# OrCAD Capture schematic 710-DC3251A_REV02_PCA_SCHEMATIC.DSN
size B; title: 3.3V TO 1.2V AT 2A 2MHz SYNCHRONOUS
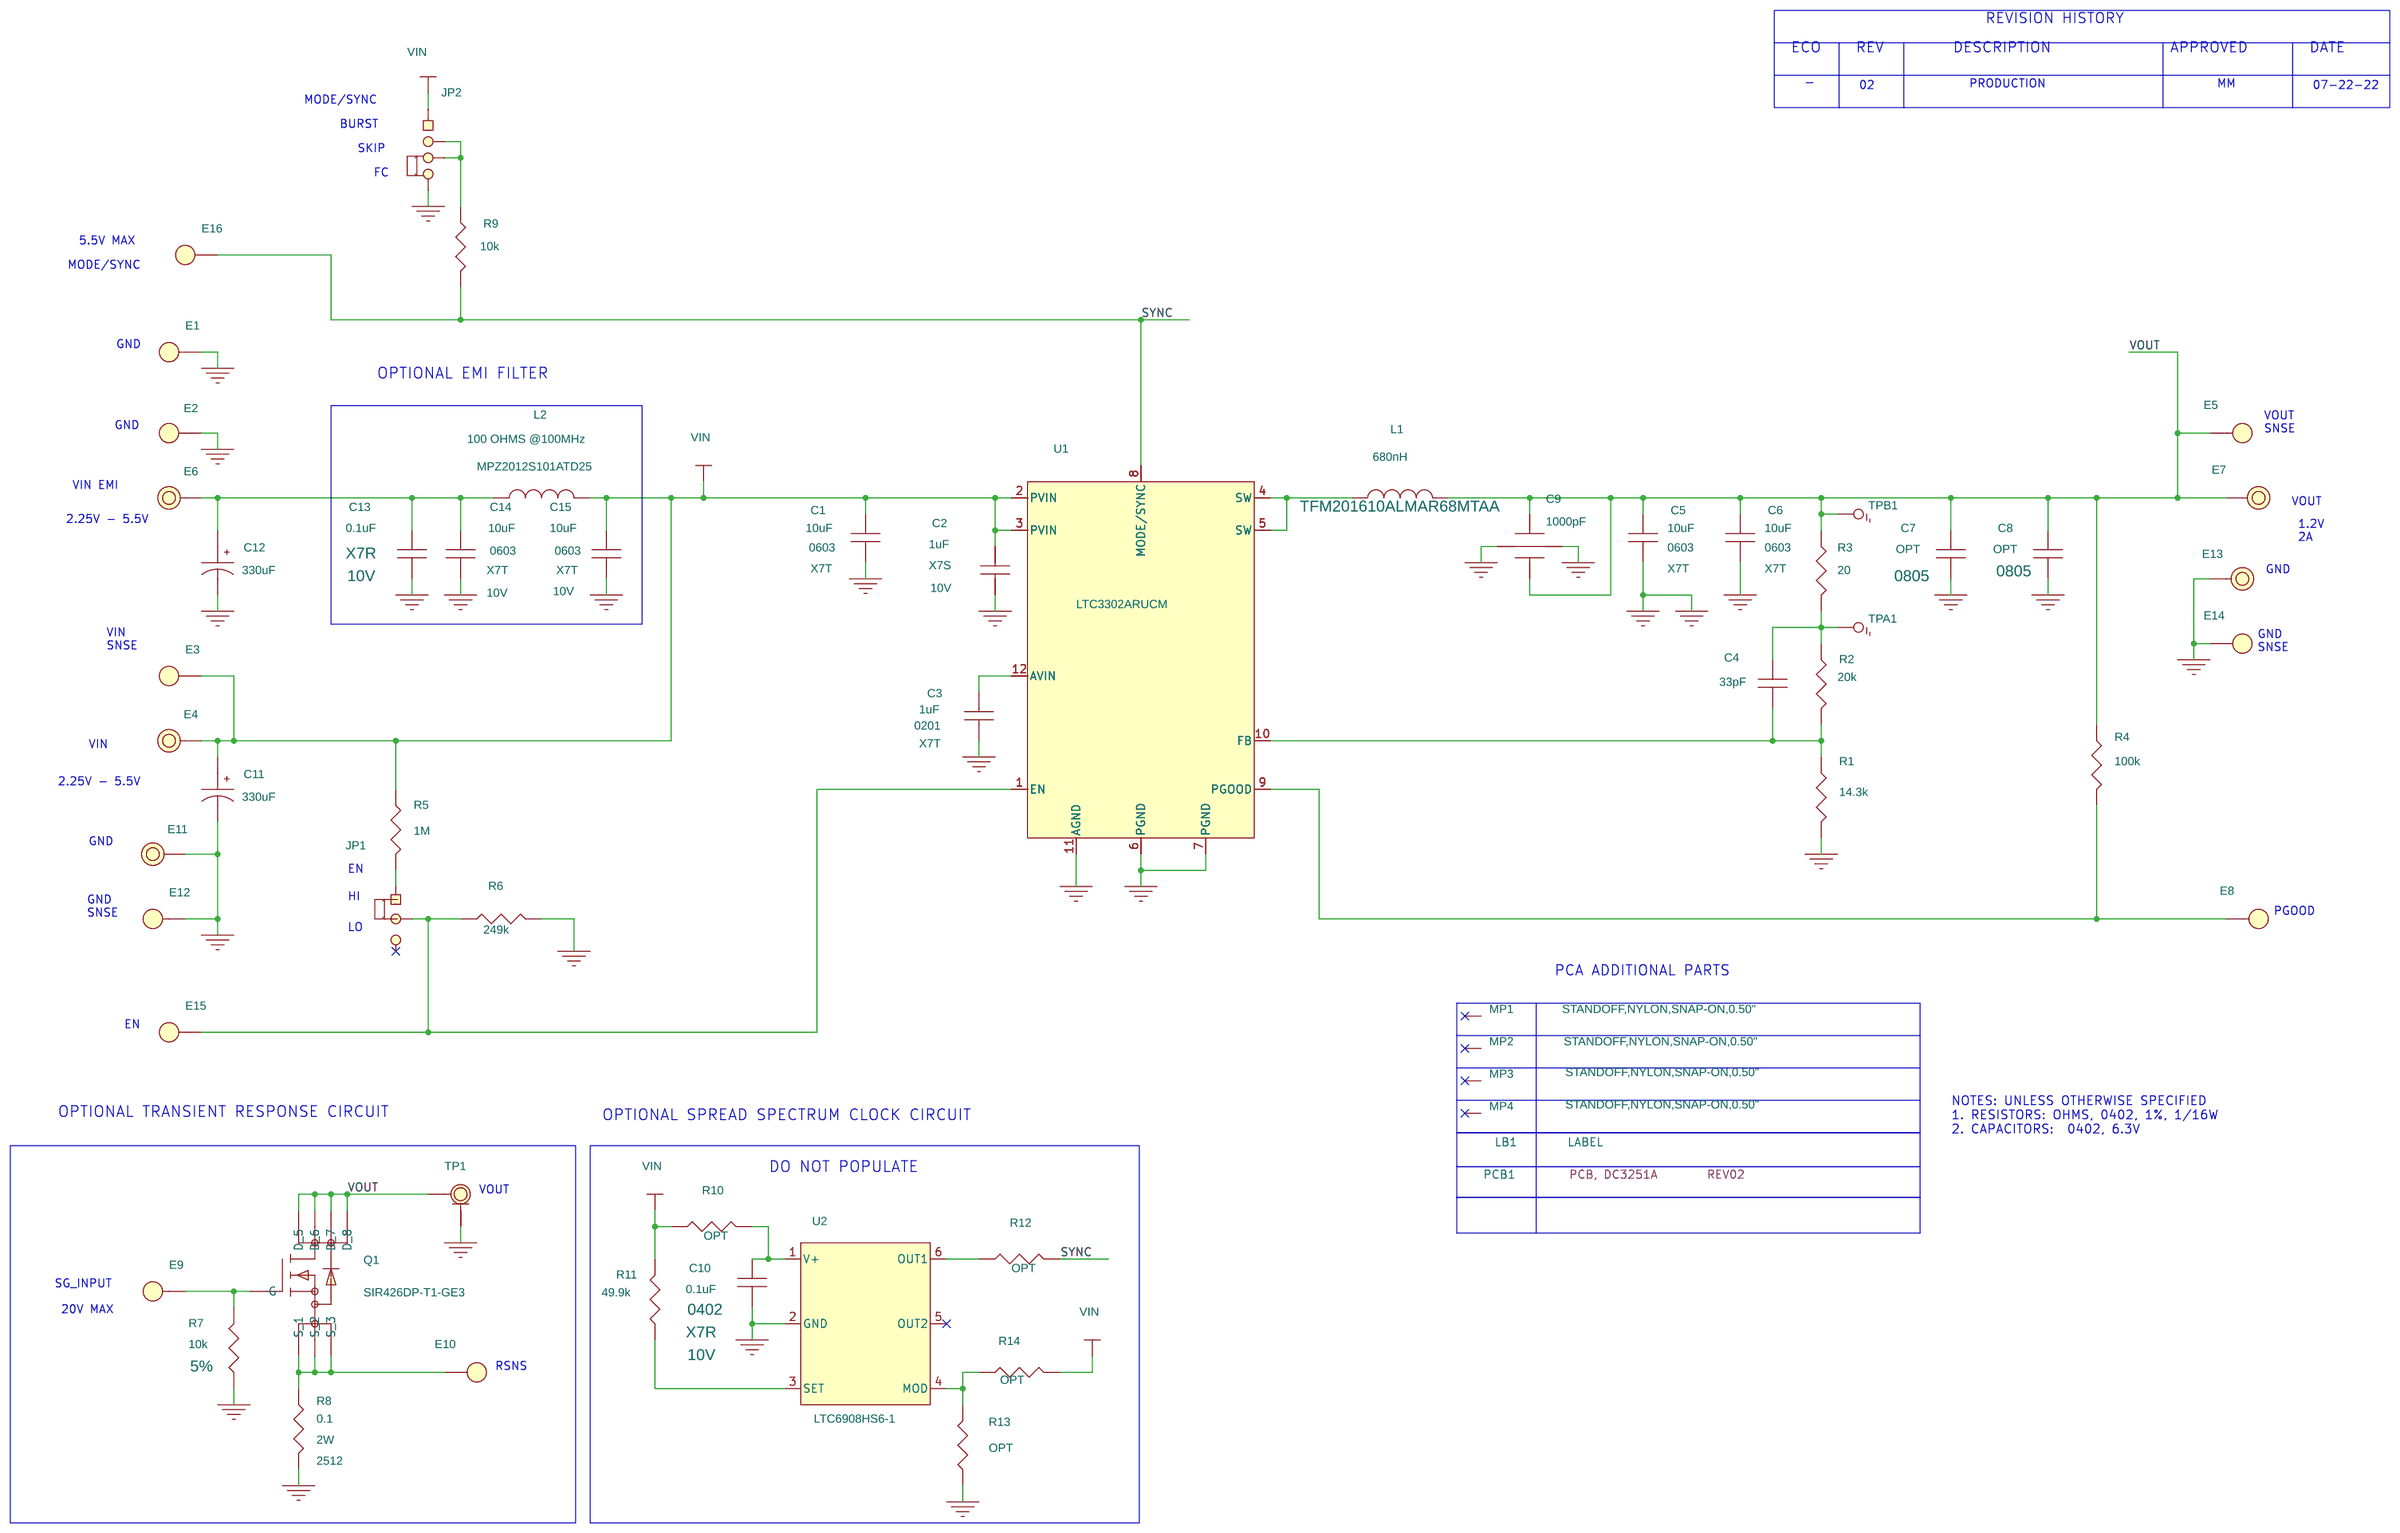
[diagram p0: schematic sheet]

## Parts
C1  10uF  [CC0603N]
C2  1uF  [CC0402N]
C3  1uF  [CC0201M]
C4  33pF  [CC0402N]
C5  10uF  [CC0603N]
C6  10uF  [CC0603N]
C7  OPT  [CC0805N]
C8  OPT  [CC0805N]
C9  1000pF  [JOHANSON-X2Y-X07]
C10  0.1uF  [CC0402N]
C11  330uF  [CAPMP7343N]
C12  330uF  [CAPMP7343N]
C13  0.1uF  [CC0402N]
C14  10uF  [CC0603N]
C15  10uF  [CC0603N]
E1  TEST POINT  [MILLMAX2308]
E2  TEST POINT  [MILLMAX2308]
E3  TEST POINT  [MILLMAX2308]
E4  TEST POINT  [MILLMAX2501]
E5  TEST POINT  [MILLMAX2308]
E6  TEST POINT  [MILLMAX2501]
E7  TEST POINT  [MILLMAX2501]
E8  TEST POINT  [MILLMAX2308]
E9  TEST POINT  [MILLMAX2308]
E10  TEST POINT  [MILLMAX2308]
E11  TEST POINT  [MILLMAX2501]
E12  TEST POINT  [MILLMAX2308]
E13  TEST POINT  [MILLMAX2501]
E14  TEST POINT  [MILLMAX2308]
E15  TEST POINT  [MILLMAX2308]
E16  TEST POINT  [MILLMAX2308]
JP1  HDR  [HD1X3-079]
JP2  HDR  [JP4X1/079]
L1  680nH  [TDK-TFM201610ALMA]
L2  100 OHMS @100MHz  [IND0805N]
LB1  LABEL  [895-0154_REV01]
MP1  STANDOFF  [MTG-8831]
MP2  STANDOFF  [MTG-8831]
MP3  STANDOFF  [MTG-8831]
MP4  STANDOFF  [MTG-8831]
PCB1  PCB, DC3251A
Q1  SIR426DP-T1-GE3  [VISHAY_PPAK_SO-8]
R1  14.3k  [CR0402N]
R2  20k  [CR0402N]
R3  20  [CR0402N]
R4  100k  [CR0402N]
R5  1M  [CR0402N]
R6  249k  [CR0402N]
R7  10k  [CR0402N]
R8  0.1  [CR2512N]
R9  10k  [CR0402N]
R10  OPT  [CR0402N]
R11  49.9k  [CR0402N]
R12  OPT  [CR0402N]
R13  OPT  [CR0402N]
R14  OPT  [CR0402N]
TP1  U.FL  [HIROSE-FL-R-SMT-1]
TPA1  COPPER FEATURE PAD  [PADSTYLE1]
TPB1  COPPER FEATURE PAD  [PADSTYLE1]
U1  LTC3302ARUCM  [LTC-UCM-12-7072]
U2  LTC6908HS6-1  [LTC-S6-6-1636]
XJP1  SHUNT
XJP2  SHUNT

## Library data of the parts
C1 C5 C6 C14 C15 = CAP: CAP.,10uF,X7T,10V,20%,0603,AEC-Q200; CLASS: DISCRETE; Dielectric Type: X7T; FPLIST: CC0603N,CC0603L,CC0603M; Inventory Qty: 0; Manufacturer: MURATA; Manufacturer PN: GRT188D71A106ME13D; PART_NUMBER: 150-1887; Package Size: 0603; Rated Voltage: 10V; Tolerance: 20%
C2 = CAP: CAP.,1uF,X7S,10V,10%,0402,AEC-Q200,NO SUBS. ALLOWED; CLASS: DISCRETE; Dielectric Type: X7S; FPLIST: CC0402N,CC0402L,CC0402M; Inventory Qty: 10000; Manufacturer: MURATA; Manufacturer PN: GCM155C71A105KE38D; PART_NUMBER: 150-0594; Package Size: 0402; Rated Voltage: 10V; Temperature Coefficient: X7S; Tolerance: 10%
C3 = CAP: CAP.,1uF,X7T,6.3V,20%,0201,AEC-Q200; CLASS: DISCRETE; Dielectric Type: X7T; FPLIST: CC0201N,CC0201L,CC0201M; Inventory Qty: 0; Manufacturer: MURATA; Manufacturer PN: GRT033D70J105ME13D; PART_NUMBER: 150-1886; Package Size: 0201; Rated Voltage: 6.3V; Tolerance: 20%
C4 = CAP: CAP.,33pF,C0G,50V,5%,0402; CLASS: DISCRETE; Dielectric Type: C0G; FPLIST: CC0402N,CC0402L,CC0402M; Inventory Qty: 24223; Manufacturer: AVX; Manufacturer PN: 04025A330JAT2A; PART_NUMBER: 150-0066; Package Size: 0402; Rated Voltage: 50V; Tolerance: 5%
C7 C8 = CAP: CAP., OPTION, 0805; CLASS: DISCRETE; FPLIST: CC0805N,CC0805L,CC0805M; PART_NUMBER: 150-3036; Package Size: 0805; Package Type: SMD
C9 = JOHANSON-X2Y: CAP.,1000pF,X7R,50V,20%,0402,3-TERM,X2Y EMI FILTER; CLASS: DISCRETE; Dielectric Type: X7R; Inventory Qty: 16829; Manufacturer: JOHANSON DIELECTRICS; Manufacturer PN: 500X07W102MV4T; PART_NUMBER: 150-1785; Package Size: 0402,3-TERM; Rated Voltage: 50V; Tolerance: 20%
C10 C13 = CAP: CAP.,0.1uF,X7R,10V,10%,0402,AEC-Q200; CLASS: DISCRETE; Dielectric Type: X7R; FPLIST: CC0402N,CC0402L,CC0402M; Inventory Qty: 59100; Manufacturer: MURATA; Manufacturer PN: GCM155R71A104KA55D; PART_NUMBER: 150-1790; Package Size: 0402; Rated Voltage: 10V; Temperature Coefficient: X7R; Tolerance: 10%
C11 C12 = CAP_P_ALT: CAP.,330uF,TANT,POSCAP,6.3V,20%,7343,25mOHMS,TPE; CLASS: DISCRETE; Dielectric Type: TANT,POSCAP; Inventory Qty: 3750; Manufacturer: PANASONIC; Manufacturer PN: 6TPE330ML; PART_NUMBER: 150-0529; Package Size: 7343; Rated Voltage: 6.3V; Tolerance: 20%; UserField01: 2400mAms, 25mOHMS
E1-E3 E5 E8-E10 E12 E14-E16 = TEST_POINT_.156_MILL-MAX_2308: TEST POINT,TURRET,0.064" MTG. HOLE,PCB 0.062" THK; CLASS: IO; Inventory Qty: 1142083; Manufacturer PN: 2308-2-00-80-00-00-07-0; PART_NUMBER: 260-0004
E4 E6 E7 E11 E13 = TESTPOINT_.219_MILL-MAX_2501: TEST POINT,TURRET,0.094" MTG. HOLE,PCB 0.062" THK; CLASS: IO; FPLIST: MILLMAX2501,MILLMAX2501-2; Inventory Qty: 823526; Manufacturer: MILL-MAX; Manufacturer PN: 2501-2-00-80-00-00-07-0; PART_NUMBER: 260-0003
JP1 = 3_PIN_HEADER_.079_SINGLE_ROW_D: CONN.,HDR,MALE,1x3,2mm,VERT,ST,THT; CLASS: IO; Inventory Qty: 22026; Manufacturer: Wurth Elektronik; Manufacturer PN: 62000311121; PART_NUMBER: 250-0484
JP2 = HD1X4-079_ALT: CONN.,HDR,MALE,1x4,2mm,VERT,ST,THT; CLASS: IO; Inventory Qty: 12591; Manufacturer: WURTH ELEKTRONIK; Manufacturer PN: 62000411121; PART_NUMBER: 250-0563
L1 = IND_ALT: IND.,680nH,PWR,20%,4.3A,53mOHMS,0806,AEC-Q200; CLASS: DISCRETE; Inventory Qty: 0; Manufacturer: TDK; Manufacturer PN: TFM201610ALMAR68MTAA; PART_NUMBER: 200-0430; Package Size: 0806; Tolerance: 20%
L2 = IND_ALT: IND.,100 OHMS @100MHz,FERRITE BEAD,25%,4A,20mOHMS,0805,AEC-Q200; CLASS: DISCRETE; FPLIST: IND0805N,IND0805L,IND0805M; Inventory Qty: 0; Manufacturer: TDK; Manufacturer PN: MPZ2012S101ATD25; PART_NUMBER: 200-0403; Package Size: 0805; Tolerance: 25%
LB1 = BLANK_LABEL: LABEL SPEC, DEMO BOARD SERIAL NUMBER; Inventory Qty: 0; Manufacturer: BRADY; Manufacturer PN: THT-96-717-10; PART_NUMBER: 895-0154
MP1-MP4 = MP-PINNED_ALT1: STANDOFF,NYLON,SNAP-ON,0.50"; CLASS: DISCRETE; Inventory Qty: 214842; Manufacturer: KEYSTONE; Manufacturer PN: 8833; PART_NUMBER: 763-0007
PCB1 = BLANK_PCB_PART: BOM Notes: REV02; CLASS: DISCRETE; Inventory Qty: 0; Manufacturer: ADI APPROVED SUPPLIER; Manufacturer PN: 600-DC3251A; PART_NUMBER: 600-DC3251A
Q1 = 8P_N-CH_TYPE1A: XSTR.,MOSFET,N-CH,40V,15.9A,PPAK SO-8; CLASS: DISCRETE; Inventory Qty: 20200; Manufacturer: VISHAY; PART_NUMBER: 240-0378; Package Size: PowerPAK® SO-8; Package Type: PPAK SO-8; Polarity: MOSFET N-Channel; Rated Power: 41.7W; Rated Voltage: 40V
R1 = RES: RES.,14.3k OHMS,1%,1/16W,0402; CLASS: DISCRETE; FPLIST: CR0402N,CR0402L,CR0402M; Inventory Qty: 9613; Manufacturer: VISHAY; Manufacturer PN: CRCW040214K3FKED; PART_NUMBER: 100-0029; Package Size: 0402; Rated Power: 1/16W; Temperature Coefficient: 100ppm; Tolerance: 1%
R2 = RES: RES.,20k OHMS,1%,1/16W,0402,AEC-Q200; CLASS: DISCRETE; FPLIST: CR0402N,CR0402L,CR0402M; Inventory Qty: 11520; Manufacturer: NIC; Manufacturer PN: NRC04F2002TRF; PART_NUMBER: 100-2549; Package Size: 0402; Rated Power: 1/16W; Temperature Coefficient: 100ppm/C; Tolerance: 1%
R3 = RES: RES.,20 OHMS,1%,1/16W,0402,AEC-Q200; CLASS: DISCRETE; FPLIST: CR0402N,CR0402L,CR0402M; Inventory Qty: 29845; Manufacturer: NIC; Manufacturer PN: NRC04F20R0TRF; PART_NUMBER: 100-0250; Package Size: 0402; Rated Power: 1/16W; Temperature Coefficient: 100ppm; Tolerance: 1%
R4 = RES: RES.,100k OHMS,5%,1/16W,0402; CLASS: DISCRETE; FPLIST: CR0402N,CR0402L,CR0402M; Inventory Qty: 91623; Manufacturer: YAGEO; Manufacturer PN: RC0402JR-07100KL; PART_NUMBER: 100-0058; Package Size: 0402; Rated Power: 1/16W; Temperature Coefficient: 100ppm/C; Tolerance: 5%
R5 = RES: RES.,1M OHM,1%,1/16W,0402,AEC-Q200; CLASS: DISCRETE; FPLIST: CR0402N,CR0402L,CR0402M; Inventory Qty: 86432; Manufacturer: STACKPOLE ELECTRONICS, INC.; Manufacturer PN: RMCF0402FT1M00; PART_NUMBER: 100-2457; Package Size: 0402; Rated Power: 1/16W; Temperature Coefficient: 100ppm; Tolerance: 1%
R6 = RES: RES.,249k OHMS,1%,1/16W,0402,AEC-Q200; CLASS: DISCRETE; FPLIST: CR0402N,CR0402L,CR0402M; Inventory Qty: 26713; Manufacturer: NIC; Manufacturer PN: NRC04F2493TRF; PART_NUMBER: 100-2663; Package Size: 0402; Rated Power: 1/16W; Temperature Coefficient: 100ppm; Tolerance: 1%
R7 = RES: RES.,10k OHMS,5%,1/10W,0402,AEC-Q200; CLASS: DISCRETE; FPLIST: CR0402N,CR0402L,CR0402M; Inventory Qty: 33211; Manufacturer: PANASONIC; Manufacturer PN: ERJ2GEJ103X; PART_NUMBER: 100-0092; Package Size: 0402; Rated Power: 1/10W; Temperature Coefficient: 200ppm/C; Tolerance: 5%
R8 = RES: RES.,0.1 OHM,1%,2W,2512,SENSE,AEC-Q200; CLASS: DISCRETE; FPLIST: CR2512N,CR2512L,CR2512M; Inventory Qty: 9640; Manufacturer: TT ELECTRONICS; Manufacturer PN: LRC-LR2512LF-01-R100-F; PART_NUMBER: 100-0553; Package Size: 2512; Rated Power: 2W; Temperature Coefficient: 100ppm; Tolerance: 1%
R9 = RES: RES.,10k OHMS,5%,1/16W,0402,AEC-Q200; CLASS: DISCRETE; FPLIST: CR0402N,CR0402L,CR0402M; Inventory Qty: 64117; Manufacturer: NIC; Manufacturer PN: NRC04J103TRF; PART_NUMBER: 100-0214; Package Size: 0402; Rated Power: 1/16W; Temperature Coefficient: 200ppm; Tolerance: 5%
R10 R12-R14 = RES: RES., OPTION, 0402; CLASS: DISCRETE; PART_NUMBER: 100-0357; Package Size: 0402
R11 = RES: RES.,49.9k OHMS,1%,1/16W,0402,AEC-Q200; CLASS: DISCRETE; FPLIST: CR0402N,CR0402L,CR0402M; Inventory Qty: 40358; Manufacturer: NIC; Manufacturer PN: NRC04F4992TRF; PART_NUMBER: 100-2406; Package Size: 0402; Rated Power: 1/16W; Temperature Coefficient: 100ppm/C; Tolerance: 1%
TP1 = HIROSE-U.FL-R-SMT-1: CONN.,U.FL,RCPT,MALE,ST,3.0x3.1mm,SMD,50 OHM; CLASS: IO; Inventory Qty: 0; Manufacturer: HIROSE ELECTRIC; Manufacturer PN: U.FL-R-SMT-1(10); PART_NUMBER: 250-0939
TPA1 TPB1 = PAD_SMALL_FILLED: TESTPOINT, PCB COPPER FEATURE; CLASS: IO; Manufacturer: N/A; Manufacturer PN: N/A; PART_NUMBER: PCBPADS-11
U1 = LTC330XARUCM: IC, 5V 2A 2MHz SYNCHRONOUS STEP-DOWN REGULATOR; CLASS: IC; Inventory Qty: 0; Manufacturer: ANALOG DEVICES, INC.; Manufacturer PN: LTC3302ARUCM#PBF; PART_NUMBER: Local-LTC3302ARUCM#PBF; Package Size: 2mmx2mm
U2 = LTC6908-S6-X: IC,OSC SILICON PROG,TSOT-23-6; CLASS: DISCRETE; Inventory Qty: 0; Manufacturer: ANALOG DEVICES; Manufacturer PN: LTC6908HS6-1#TRMPBF; PART_NUMBER: LTC6908HS6-1#PBF; Package Size: SOT-23-6 Thin, TSOT-23-6; Package Type: TSOT-23-6
XJP1 XJP2 = CONN_SHUNT_2_POS_2mm: CONN.,SHUNT,FEMALE,2-POS,2mm; CLASS: IO; Inventory Qty: 64675; Manufacturer: Wurth Elektronik; Manufacturer PN: 60800213421; PART_NUMBER: 250-0485

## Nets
GND: C1.2 C2.2 C3.2 C5.2 C6.2 C7.2 C8.2 C9.3(G1) C9.4(G2) C10.2 C11.2 C12.2 C13.2 C14.2 C15.2 E1.1(A) E2.1(A) E11.1 E12.1(A) E13.1 E14.1(A) JP2.4 R1.1 R6.2 R7.2 R8.2 R13.2 TP1.2(GND) TP1.3(GND) TP1.4(GND) TP1.5(GND) U1.6(PGND) U1.7(PGND) U1.11(AGND) U2.2(GND)
VIN: C1.1 C2.1 C11.1 C15.1 E3.1(A) E4.1 JP2.1 L2.2 R5.1 R10.2 R11.1 R14.1 U1.2(PVIN) U1.3(PVIN)
SYNC: E16.1(A) R9.2 R12.1 U1.8(MODE/SYNC)
VOUT: C5.1 C6.1 C7.1 C8.1 C9.1(A) C9.2(B) E5.1(A) E7.1 L1.2 Q1.5(D) Q1.6(D) Q1.7(D) Q1.8(D) R3.1 R4.1 TP1.1 TPB1.1
N16763174: L1.1 U1.4(SW) U1.5(SW)
N16763234: C4.2 R1.2 R2.2 U1.10(FB)
N16763242: E15.1(A) JP1.2 R6.1 U1.1(EN)
N16763412: C4.1 R2.1 R3.2 TPA1.1
N16763484: E8.1(A) R4.2 U1.9(PGOOD)
N16763862: JP1.1 R5.2
N16886451: C12.1 C13.1 C14.1 E6.1 L2.1
N16918546: E9.1(A) Q1.4(G) R7.1
N16918561: E10.1(A) Q1.1(S) Q1.2(S) Q1.3(S) R8.1
N16980586: C3.1 U1.12(AVIN)
N16981375: JP2.2 JP2.3 R9.1
N17014275: C10.1 R10.1 U2.1(V+)
N17014573: R11.2 U2.3(SET)
N17014578: R12.2 U2.6(OUT1)
N17015779: R13.1 R14.2 U2.4(MOD)

Not connected (* = marked no-connect by the designer): JP1 3*; MP1 1*; MP2 1*; MP3 1*; MP4 1*; U2 5(OUT2)*

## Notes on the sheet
- REVISION HISTORY
- ECO
- REV
- DESCRIPTION
- APPROVED
- DATE
- -
- PRODUCTION
- MM
- MODE/SYNC
- 02
- 07-22-22
- BURST
- SKIP
- FC
- 5.5V MAX
- MODE/SYNC
- GND
- OPTIONAL EMI FILTER
- GND
- VOUT
  SNSE
- VIN EMI
- VOUT
- 2.25V - 5.5V
- 1.2V
  2A
- GND
- VIN
  SNSE
- GND
  SNSE
- VIN
- 2.25V - 5.5V
- GND
- EN
- GND
  SNSE
- HI
- PGOOD
- LO
- PCA ADDITIONAL PARTS
- EN
- OPTIONAL TRANSIENT RESPONSE CIRCUIT
- OPTIONAL SPREAD SPECTRUM CLOCK CIRCUIT
- NOTES: UNLESS OTHERWISE SPECIFIED
  1. RESISTORS: OHMS, 0402, 1%, 1/16W
  2. CAPACITORS:  0402, 6.3V
- DO NOT POPULATE
- VOUT
- SG_INPUT
- 20V MAX
- RSNS
